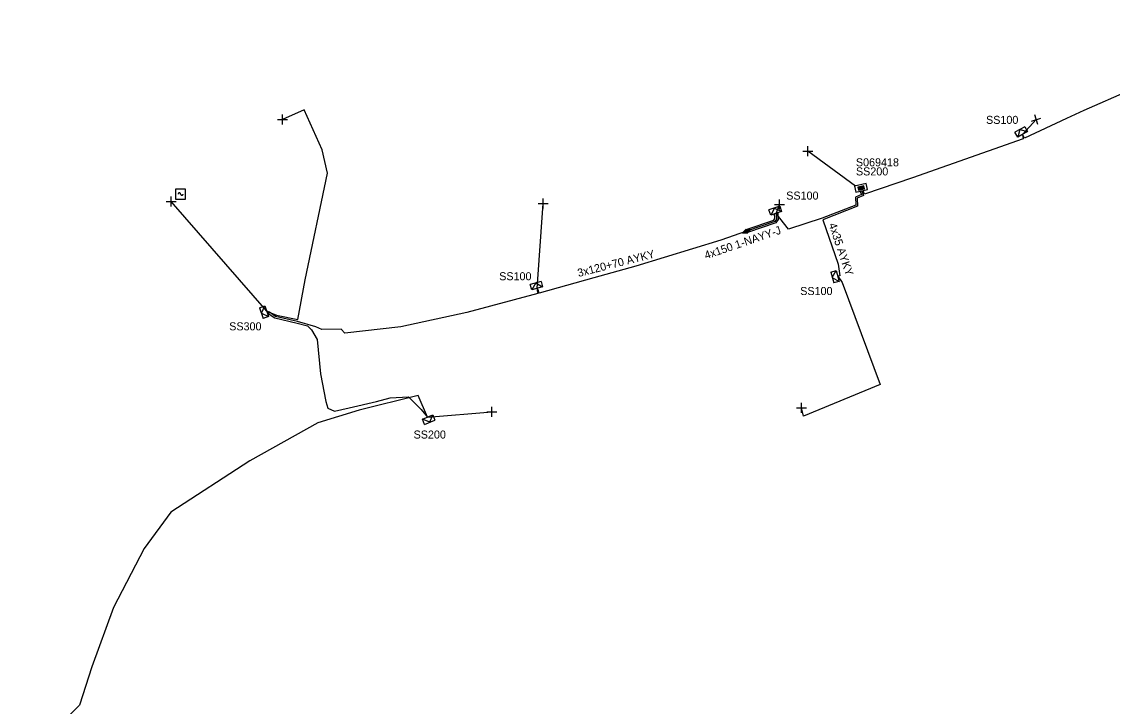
# Model space of a CAD drawing. Extents: x -763093 to -760976, y -1155572 to -1152009.
# Drawn here: x -761801.7 to -761666.2, y -1152551.4 to -1152466.3 of the extents above; entities that cross this region are included whole.
import ezdxf

# ---------------------------------------------------------------- set-up
doc = ezdxf.new("R2010")
doc.units = 0
for name, color, linetype in [('Vrstva 1', 7, 'Continuous'), ('Vrstva 19', 7, 'Continuous'), ('Vrstva 20', 7, 'Continuous'), ('Vrstva 28', 7, 'Continuous'), ('Vrstva 29', 7, 'Continuous'), ('Vrstva 30', 7, 'Continuous'), ('Vrstva 31', 7, 'Continuous'), ('Vrstva 33', 7, 'Continuous'), ('Vrstva 34', 7, 'Continuous'), ('Vrstva 4', 7, 'Continuous'), ('Vrstva 5', 7, 'Continuous'), ('Vrstva 52', 7, 'Continuous'), ('Vrstva 54', 7, 'Continuous'), ('Vrstva 59', 7, 'Continuous'), ('Vrstva 6', 7, 'Continuous'), ('Vrstva 8', 7, 'Continuous'), ('Vrstva 9', 7, 'Continuous')]:
    doc.layers.add(name, color=color, linetype=linetype)

# ---------------------------------------------------------------- blocks, each defined once
blk = doc.blocks.new('NN870')
at = {"layer": 'Vrstva 4'}
for points in [[(0, -0.25), (0.5, 0), (0, 0.25), (-0.5, 0), (0, -0.25)], [(0.37, 0), (0, 0.19), (-0.36, 0), (0, -0.19), (0.37, 0)], [(0.24, 0), (0, 0.12), (-0.25, 0), (0, -0.12), (0.24, 0)], [(0.12, 0), (0, 0.06), (-0.13, 0), (0, -0.06), (0.12, 0)]]:
    blk.add_lwpolyline(points, dxfattribs=at)
blk = doc.blocks.new('NN800')
at = {"layer": 'Vrstva 1'}
for points in [[(-0.44, 0.44), (0.44, -0.44)], [(-0.44, -0.44), (0.44, 0.44)]]:
    blk.add_lwpolyline(points, dxfattribs=at)
blk = doc.blocks.new('NN620')
at = {"layer": 'Vrstva 8'}
for points in [[(0.75, 0), (-0.75, 0)], [(-0.75, 0), (-0.75, -0.75)], [(0.75, -0.75), (0.75, 0)], [(-0.75, -0.75), (0.75, -0.75)], [(0.37, -0.18), (-0.38, -0.18)], [(-0.38, -0.18), (-0.38, -0.56)], [(-0.38, -0.56), (0.37, -0.56)], [(0.32, -0.23), (-0.33, -0.23)], [(-0.33, -0.23), (-0.33, -0.51)], [(-0.33, -0.51), (0.32, -0.51)], [(0.27, -0.27), (-0.28, -0.27)], [(-0.28, -0.27), (-0.28, -0.46)], [(-0.28, -0.46), (0.27, -0.46)], [(0.23, -0.32), (-0.23, -0.32)], [(-0.23, -0.32), (-0.23, -0.42)], [(-0.23, -0.42), (0.23, -0.42)], [(-0.19, -0.37), (0.19, -0.37)], [(0.23, -0.42), (0.23, -0.32)], [(0.27, -0.46), (0.27, -0.27)], [(0.32, -0.51), (0.32, -0.23)], [(0.37, -0.56), (0.37, -0.18)]]:
    blk.add_lwpolyline(points, dxfattribs=at)
blk = doc.blocks.new('NN630')
at = {"layer": 'Vrstva 9'}
for points in [[(0, -0.7), (-0.7, 0)], [(-0.7, -0.7), (-0.7, 0), (0.7, 0), (0.7, -0.7)], [(-0.7, -0.7), (0.7, -0.7)], [(0, -0.7), (0.7, 0)]]:
    blk.add_lwpolyline(points, dxfattribs=at)
blk = doc.blocks.new('NN740')
at = {"layer": 'Vrstva 1'}
for points in [[(0.62, 0.62), (-0.63, 0.62)], [(-0.63, 0.62), (-0.63, -0.63)], [(0, 0), (0, 0.01), (0, 0.03), (-0.01, 0.05), (-0.01, 0.06), (-0.02, 0.08), (-0.03, 0.09), (-0.04, 0.1), (-0.05, 0.11), (-0.06, 0.12), (-0.08, 0.13), (-0.09, 0.14), (-0.11, 0.14), (-0.12, 0.15), (-0.14, 0.15), (-0.15, 0.15), (-0.17, 0.15), (-0.18, 0.15), (-0.2, 0.15), (-0.21, 0.14), (-0.23, 0.13), (-0.24, 0.12), (-0.26, 0.11), (-0.27, 0.1), (-0.28, 0.09), (-0.29, 0.08), (-0.29, 0.06), (-0.3, 0.05), (-0.3, 0.03), (-0.31, 0.02), (-0.31, 0), (-0.31, 0)], [(0.62, -0.63), (0.62, 0.62)], [(-0.63, -0.63), (0.62, -0.63)], [(0, 0), (0, -0.02), (0, -0.03), (0.01, -0.05), (0.01, -0.06), (0.02, -0.08), (0.03, -0.09), (0.04, -0.1), (0.05, -0.11), (0.06, -0.12), (0.07, -0.13), (0.09, -0.14), (0.1, -0.15), (0.12, -0.15), (0.13, -0.15), (0.15, -0.15), (0.16, -0.15), (0.18, -0.15), (0.19, -0.15), (0.21, -0.14), (0.22, -0.14), (0.24, -0.13), (0.25, -0.12), (0.26, -0.11), (0.27, -0.09), (0.28, -0.08), (0.29, -0.07), (0.29, -0.05), (0.3, -0.04), (0.3, -0.02), (0.3, -0.01), (0.3, -0.01)]]:
    blk.add_lwpolyline(points, dxfattribs=at)

msp = doc.modelspace()

# ---------------------------------------------------------------- linework, layer by layer
at = {"layer": 'Vrstva 20'}
msp.add_lwpolyline([(-761708.13, -1152490.11), (-761707.73, -1152490.09), (-761707.68, -1152490.87), (-761707.97, -1152491.29), (-761711.5, -1152492.5), (-761711.63, -1152492.12), (-761708.23, -1152490.95), (-761708.08, -1152490.75)], close=True, dxfattribs=at)
at = {"layer": 'Vrstva 5'}
for points in [[(-761641.29, -1152466.27), (-761641.09, -1152466.87), (-761641.67, -1152467.01), (-761646, -1152468.58), (-761653.53, -1152470.98), (-761663.99, -1152474.81), (-761669.68, -1152477.3), (-761671.82, -1152478.31), (-761677.04, -1152480.76), (-761677.28, -1152480.27), (-761677.22, -1152480.83), (-761690.99, -1152485.68), (-761696.92, -1152487.72), (-761697.11, -1152487.28)], [(-761697.47, -1152487.36), (-761697.33, -1152487.77), (-761698.06, -1152488.07), (-761698.03, -1152489.06), (-761702.19, -1152490.71), (-761706.38, -1152492.07), (-761707.93, -1152490.1)], [(-761707.93, -1152490.1), (-761707.88, -1152490.81), (-761708.1, -1152491.12), (-761711.62, -1152492.33)], [(-761711.62, -1152492.33), (-761714.79, -1152493.42), (-761725.37, -1152496.66), (-761730.59, -1152498.11), (-761737.36, -1152500.02), (-761737.45, -1152499.68), (-761737.62, -1152499.43), (-761737.64, -1152499.74), (-761737.56, -1152500.08), (-761746.39, -1152502.44), (-761754.59, -1152504.22), (-761761.52, -1152505), (-761762.01, -1152504.5), (-761764.39, -1152504.53), (-761765.14, -1152504.23), (-761767.4, -1152503.55), (-761770.16, -1152502.91), (-761770.9, -1152502.4), (-761771.25, -1152502.27)], [(-761771.25, -1152502.27), (-761770.93, -1152502.62), (-761770.24, -1152503.09), (-761767.45, -1152503.75), (-761766.18, -1152504.07), (-761765.66, -1152504.58), (-761764.97, -1152505.8), (-761764.56, -1152510.05), (-761763.89, -1152513.5), (-761763.64, -1152514.33), (-761762.83, -1152514.71), (-761760.99, -1152514.3), (-761757.58, -1152513.5), (-761755.92, -1152513.06), (-761753.61, -1152512.91), (-761752.03, -1152514.51), (-761751.25, -1152515.44)]]:
    msp.add_lwpolyline(points, dxfattribs=at)
at = {"layer": 'Vrstva 52'}
for points in [[(-761697.28, -1152487.32), (-761697.08, -1152487.88), (-761697.86, -1152488.21), (-761697.83, -1152489.2), (-761702.12, -1152490.9), (-761700.22, -1152496.43), (-761700.01, -1152497.88), (-761700.27, -1152497.9)], [(-761751.25, -1152515.44), (-761752.43, -1152512.76), (-761759.76, -1152514.56), (-761764.88, -1152516.14), (-761773.35, -1152520.87), (-761783.17, -1152527.25), (-761786.46, -1152531.8), (-761790.31, -1152539.13), (-761792.98, -1152546.51), (-761794.5, -1152551.26), (-761795.93, -1152552.67), (-761798.92, -1152562.83), (-761801.69, -1152574.76), (-761799.48, -1152575.58)]]:
    msp.add_lwpolyline(points, dxfattribs=at)
at = {"layer": 'Vrstva 59'}
for points in [[(-761771.25, -1152502.27), (-761770.03, -1152502.78), (-761767.36, -1152503.31), (-761766.48, -1152498.38), (-761763.69, -1152485.09), (-761764.35, -1152482.2), (-761766.58, -1152477.21), (-761769.27, -1152478.43)], [(-761677.28, -1152480.27), (-761675.6, -1152478.44)], [(-761698.06, -1152486.72), (-761704, -1152482.38)], [(-761771.25, -1152502.27), (-761783.13, -1152488.63)], [(-761737.62, -1152499.43), (-761736.88, -1152488.88)], [(-761707.93, -1152490.1), (-761707.52, -1152489.01)], [(-761700.27, -1152497.9), (-761699.71, -1152498.69), (-761694.98, -1152511.37), (-761704.54, -1152515.33), (-761704.79, -1152514.28)], [(-761751.25, -1152515.44), (-761743.28, -1152514.77)]]:
    msp.add_lwpolyline(points, dxfattribs=at)

# ---------------------------------------------------------------- block references
at = {"layer": 'Vrstva 19', "rotation": 21.196344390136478}
msp.add_blockref('NN870', (-761711.62, -1152492.33), dxfattribs=at)
at = {"layer": 'Vrstva 28', "rotation": -167.09456674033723}
msp.add_blockref('NN620', (-761697.28, -1152487.3), dxfattribs=at)
at = {"layer": 'Vrstva 31'}
for p, rotation in [((-761677.28, -1152480.27), -150.89279993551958), ((-761707.93, -1152490.1), -162.0449027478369), ((-761700.27, -1152497.9), -74.60354171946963), ((-761737.62, -1152499.43), -164.6206305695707), ((-761771.25, -1152502.27), -70.19739727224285), ((-761751.25, -1152515.44), 22.599378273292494)]:
    msp.add_blockref('NN630', p, dxfattribs=dict(at, rotation=rotation))
at = {"layer": 'Vrstva 34'}
for p, rotation in [((-761769.27, -1152478.43), 44.99999995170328), ((-761675.6, -1152478.44), 62.406823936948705), ((-761704, -1152482.38), 45), ((-761783.13, -1152488.63), 45), ((-761736.88, -1152488.88), 45), ((-761707.52, -1152489.01), 45), ((-761743.28, -1152514.77), 45), ((-761704.79, -1152514.28), 45)]:
    msp.add_blockref('NN800', p, dxfattribs=dict(at, rotation=rotation))
msp.add_blockref('NN740', (-761781.95, -1152487.7), dxfattribs=at)

# ---------------------------------------------------------------- texts
at = {"layer": 'Vrstva 29'}
msp.add_text('S069418', height=1, dxfattribs=at).set_placement((-761698.01, -1152484.25))
at = {"layer": 'Vrstva 30'}
msp.add_text('SS200', height=1, dxfattribs=at).set_placement((-761698, -1152485.38))
at = {"layer": 'Vrstva 33'}
for s, p in [('SS100', (-761681.83, -1152478.97)), ('SS100', (-761706.67, -1152488.39)), ('SS100', (-761742.35, -1152498.42)), ('SS100', (-761704.93, -1152500.26)), ('SS300', (-761775.91, -1152504.65)), ('SS200', (-761752.99, -1152518.11))]:
    msp.add_text(s, height=1, dxfattribs=at).set_placement(p)
at = {"layer": 'Vrstva 54'}
msp.add_text('4x35 AYKY', height=1, rotation=288.663, dxfattribs=at).set_placement((-761701.42, -1152491.47))
at = {"layer": 'Vrstva 6'}
for s, rotation, p in [('4x150 1-NAYY-J', 18.97, (-761716.64, -1152495.83)), ('3x120+70 AYKY', 14.334, (-761732.48, -1152498.02))]:
    msp.add_text(s, height=1, rotation=rotation, dxfattribs=at).set_placement(p)

doc.saveas('drawing.dxf')
